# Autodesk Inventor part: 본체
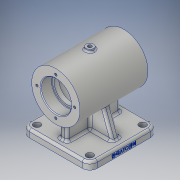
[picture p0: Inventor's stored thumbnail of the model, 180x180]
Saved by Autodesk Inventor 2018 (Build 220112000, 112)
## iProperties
Created: 2019-06
Part Number: 본체
Material: 알루미늄 6061
Document SubType Name: Modeling
Designer: Administrator
Density: 2.7 g/cm^3
Appearance: 알루미늄 - 평지
Mass: 609.502 g
Surface Area: 624.818 cm^2
Volume: 225.741 cm^3
Author: Administrator
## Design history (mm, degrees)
sketch "스케치1"
  geometry: C1 r 32 at (0, 0); 1 further point
  constraints: 1 centre point, 1 coincident
  dimensions: "d0" = 64 diameter of C1
extrude "돌출1" new body sketch "스케치1" stored distance "d1" = 90; taper "d2" = 0 deg
node "작업 평면1"
sketch "스케치2"
  geometry: L1 (45, 45)-(-45, 45); L2 (-45, 45)-(-45, -45); L3 (-45, -45)-(45, -45); L4 (45, -45)-(45, 45); L5 (45, 45)-(-45, -45); L6 (-45, 45)-(45, -45); 1 further point
  constraints: 12 end point, 2 midpoint, 2 parallel, 1 horizontal, 1 perpendicular
  dimensions: "d4" = 90 distance of L2.end L3.end; "d5" = 90 distance of L1.end L2.end
extrude "돌출2" join sketch "스케치2" distance "d6" = 10; taper "d7" = 0 deg
sketch "스케치3"
  geometry: L1 (45, -55)-(-45, -55) reference; L2 (-35, -55)-(-23.058, -22.189); L3 (-45, -65)-(-45, -55) reference; L4 (35, -55)-(23.058, -22.189); L5 (45, -65)-(45, -55) reference; L6 (-35, -55)-(35, -55); A1 r 32 centre (0, 0) between (-23.058, -22.189) and (23.058, -22.189); 1 further point
  constraints: 6 end point, 2 point on circle, 2 point on line, 1 centre point, 1 coincident, 1 collinear
  dimensions: "d8" = 110 deg angle of L2 L1; "d9" = 10 distance from line of L2.start L3; "d10" = 10 distance from line of L4.start L5; "d11" = 110 deg angle of L1 L4; "d12" = 64 diameter of A1
extrude "돌출3" join sketch "스케치3" stored distance "d13" = 10; taper "d14" = 0 deg
sketch "스케치4"
  geometry: L1 (-5, -35)-(5, -35); L2 (5, -35)-(5, 35); L3 (5, 35)-(-5, 35); L4 (-5, 35)-(-5, -35); L5 (-5, -35)-(5, 35); L6 (5, -35)-(-5, 35); 1 further point
  constraints: 12 end point, 2 midpoint, 2 parallel, 1 horizontal, 1 perpendicular
  dimensions: "d15" = 10 distance of L2.end L3.end; "d16" = 70 distance of L1.end L2.end
extrude "돌출4" join sketch "스케치4" stored distance "d17" = 10; taper "d18" = 0 deg
sketch "스케치5"
  geometry: L1 (0, 73.372)-(0, -73.372); L2 (20, 45)-(20, 30.6); L3 (19.4, 30)-(17, 30); L4 (17, 30)-(17, 24); L5 (17, 24)-(22, 24); L6 (25, 21)-(25, -21); L7 (22, -24)-(17, -24); L8 (17, -24)-(17, -30); L9 (17, -30)-(19.4, -30); L10 (20, -30.6)-(20, -45); L11 (-32, -45)-(32, -45) reference; L12 (20, -45)-(0, -45); L13 (32, 45)-(-32, 45) reference; L14 (0, 45)-(0, -45); L15 (0, 45)-(20, 45); A1 r 3 centre (22, -21) between (22, -24) and (25, -21); A2 r 3 centre (22, 21) between (25, 21) and (22, 24); A3 r 0.6 centre (19.4, -30.6) between (20, -30.6) and (19.4, -30); A4 r 0.6 centre (19.4, 30.6) between (19.4, 30) and (20, 30.6); 8 further points
  constraints: 26 end point, 12 point on line, 8 point on circle, 8 tangent, 7 perpendicular, 5 midpoint, 4 centre point, 3 vertical, 2 equal radius, 1 coincident, 1 collinear, 1 horizontal alignment
  dimensions: "d19" = 15 distance of L2.start point (20, 30); "d20" = 15 distance of point (20, -30) L10.end; "d21" = 48 distance of point (25, 24) point (25, -24); "d22" = 40 diameter of L2 L1; "d23" = 34 diameter of L4 L1; "d24" = 50 diameter of L6 L1; "d25" = 3 radius of A1 (derived); "d26" = 0.6 radius of A3
revolve "회전1" sketch "스케치5" stored, may be unused: angle "d27" = 90 deg
chamfer "모따기1" distance "d28" = 1; stored, may be unused: second distance "d29" = 2, angle "d30" = 45 deg
node "작업 평면2"
sketch "스케치6"
  geometry: C1 r 5 at (0, 0); 1 further point
  constraints: 1 centre point, 1 coincident
  dimensions: "d32" = 10 diameter of C1
extrude "돌출5" join sketch "스케치6" stored distance "d33" = 10; taper "d34" = 0 deg
sketch "스케치7"
  geometry: C1 r 5 at (0, 0) reference; 2 further points
  constraints: 1 coincident
hole "구멍1" sketch "스케치7" at (0, 0) diameter "d35" = 4.917; stored, may be unused: countersink angle "d39" = 90 deg, drill point angle "d41" = 118 deg; dims "d36" = 12, "d37" = 4, "d38" = 2, "d40" = 17.1
sketch "스케치8"
  geometry: C1 r 25 at (0, 0); 3 further points
  constraints: 2 vertical alignment, 1 centre point, 1 coincident, 1 other
  dimensions: "d42" = 50 diameter of C1
hole "구멍2" sketch "스케치8" at (0, 25) diameter "d43" = 3.242; stored, may be unused: countersink angle "d47" = 90 deg, drill point angle "d49" = 118 deg; dims "d44" = 7, "d45" = 4, "d46" = 2, "d48" = 9
fillet "모깎기1" dims "d53" = 10
sketch "스케치9"
  geometry: C1 r 4.5 at (-35, 35); C2 r 4.5 at (35, 35); C3 r 4.5 at (-35, -35); C4 r 4.5 at (35, -35); A1 r 10 centre (-35, 35) between (-35, 45) and (-45, 35) reference; A2 r 10 centre (35, 35) between (45, 35) and (35, 45) reference; A3 r 10 centre (-35, -35) between (-45, -35) and (-35, -45) reference; A4 r 10 centre (35, -35) between (35, -45) and (45, -35) reference; 1 further point
  constraints: 4 centre point, 4 coincident
  dimensions: "d54" = 9 diameter of C1; "d55" = 9 diameter of C2; "d56" = 9 diameter of C4; "d57" = 9 diameter of C3
extrude "돌출6" cut sketch "스케치9" distance "d58" = 10; taper "d59" = 0 deg
fillet "모깎기2" dims "d60" = 3
fillet "모깎기3" dims "d61" = 3
fillet "모깎기4" dims "d62" = 3
fillet "모깎기5" dims "d63" = 3
fillet "모깎기6" dims "d64" = 3
fillet "모깎기7" dims "d65" = 3
fillet "모깎기8" dims "d66" = 3
fillet "모깎기9" dims "d67" = 2
sketch "스케치10"
  geometry: L1 (0, 0)-(70, 0) reference; 2 further points
  constraints: 1 vertical alignment, 1 other
  dimensions: "d68" = 4 distance from line of point (35, 4) L1
feature "엠보싱1" sketch "스케치10" dims "d2" = 0, "d69" = 0.5, "d70" = 0
sketch "스케치11"
  geometry: L1 (22.155, 40)-(-22.155, 40); L2 (-40, 22.155)-(-40, -22.155); L3 (-22.155, -40)-(22.155, -40); L4 (40, -22.155)-(40, 22.155); L5 (40, 40)-(-40, -40); L6 (-40, 40)-(40, -40); C1 r 4.5 at (35, -35) reference; C2 r 4.5 at (35, 35) reference; C3 r 4.5 at (-35, 35) reference; A1 r 10 centre (35, -35) between (36.538, -25.119) and (25.119, -36.538); A2 r 10 centre (35, 35) between (25.119, 36.538) and (36.538, 25.119); A3 r 10 centre (-35, 35) between (-36.538, 25.119) and (-25.119, 36.538); A4 r 10 centre (-35, -35) between (-45, -35) and (-35, -45) reference; A5 r 10 centre (-35, -35) between (-25.119, -36.538) and (-36.538, -25.119); A6 r 3 centre (37, -22.155) between (36.538, -25.119) and (40, -22.155); A7 r 3 centre (22.155, -37) between (22.155, -40) and (25.119, -36.538); A8 r 3 centre (-22.155, -37) between (-25.119, -36.538) and (-22.155, -40); A9 r 3 centre (-37, -22.155) between (-40, -22.155) and (-36.538, -25.119); A10 r 3 centre (-22.155, 37) between (-22.155, 40) and (-25.119, 36.538); A11 r 3 centre (-37, 22.155) between (-36.538, 25.119) and (-40, 22.155); A12 r 3 centre (22.155, 37) between (25.119, 36.538) and (22.155, 40); A13 r 3 centre (37, 22.155) between (40, 22.155) and (36.538, 25.119); 10 further points
  constraints: 32 point on circle, 16 tangent, 12 centre point, 12 end point, 8 point on line, 7 equal radius, 4 coincident, 2 midpoint, 2 parallel, 1 horizontal, 1 perpendicular
  dimensions: "d71" = 80 distance of L5.end L6.end; "d72" = 80 distance of L6.start L5.end; "d73" = 20 diameter of A1; "d74" = 10 radius of A2; "d75" = 10 radius of A3; "d76" = 10 radius of A5; "d77" = 3 radius of A6; "d78" = 44.30953 distance of L3.start L3.end; "d79" = 44.30953 distance of L4.start L4.end; "d80" = 44.30953 distance of L2.start L2.end; "d81" = 44.30953 distance of L1.start L1.end
extrude "돌출7" cut sketch "스케치11" distance "d82" = 5; taper "d83" = 0 deg
node "솔리드1"
pattern_circular "원형 패턴1" dims angle "d51" = 360 deg
mirror "미러1"
other parameters: "d3" = -65, "d31" = 35
